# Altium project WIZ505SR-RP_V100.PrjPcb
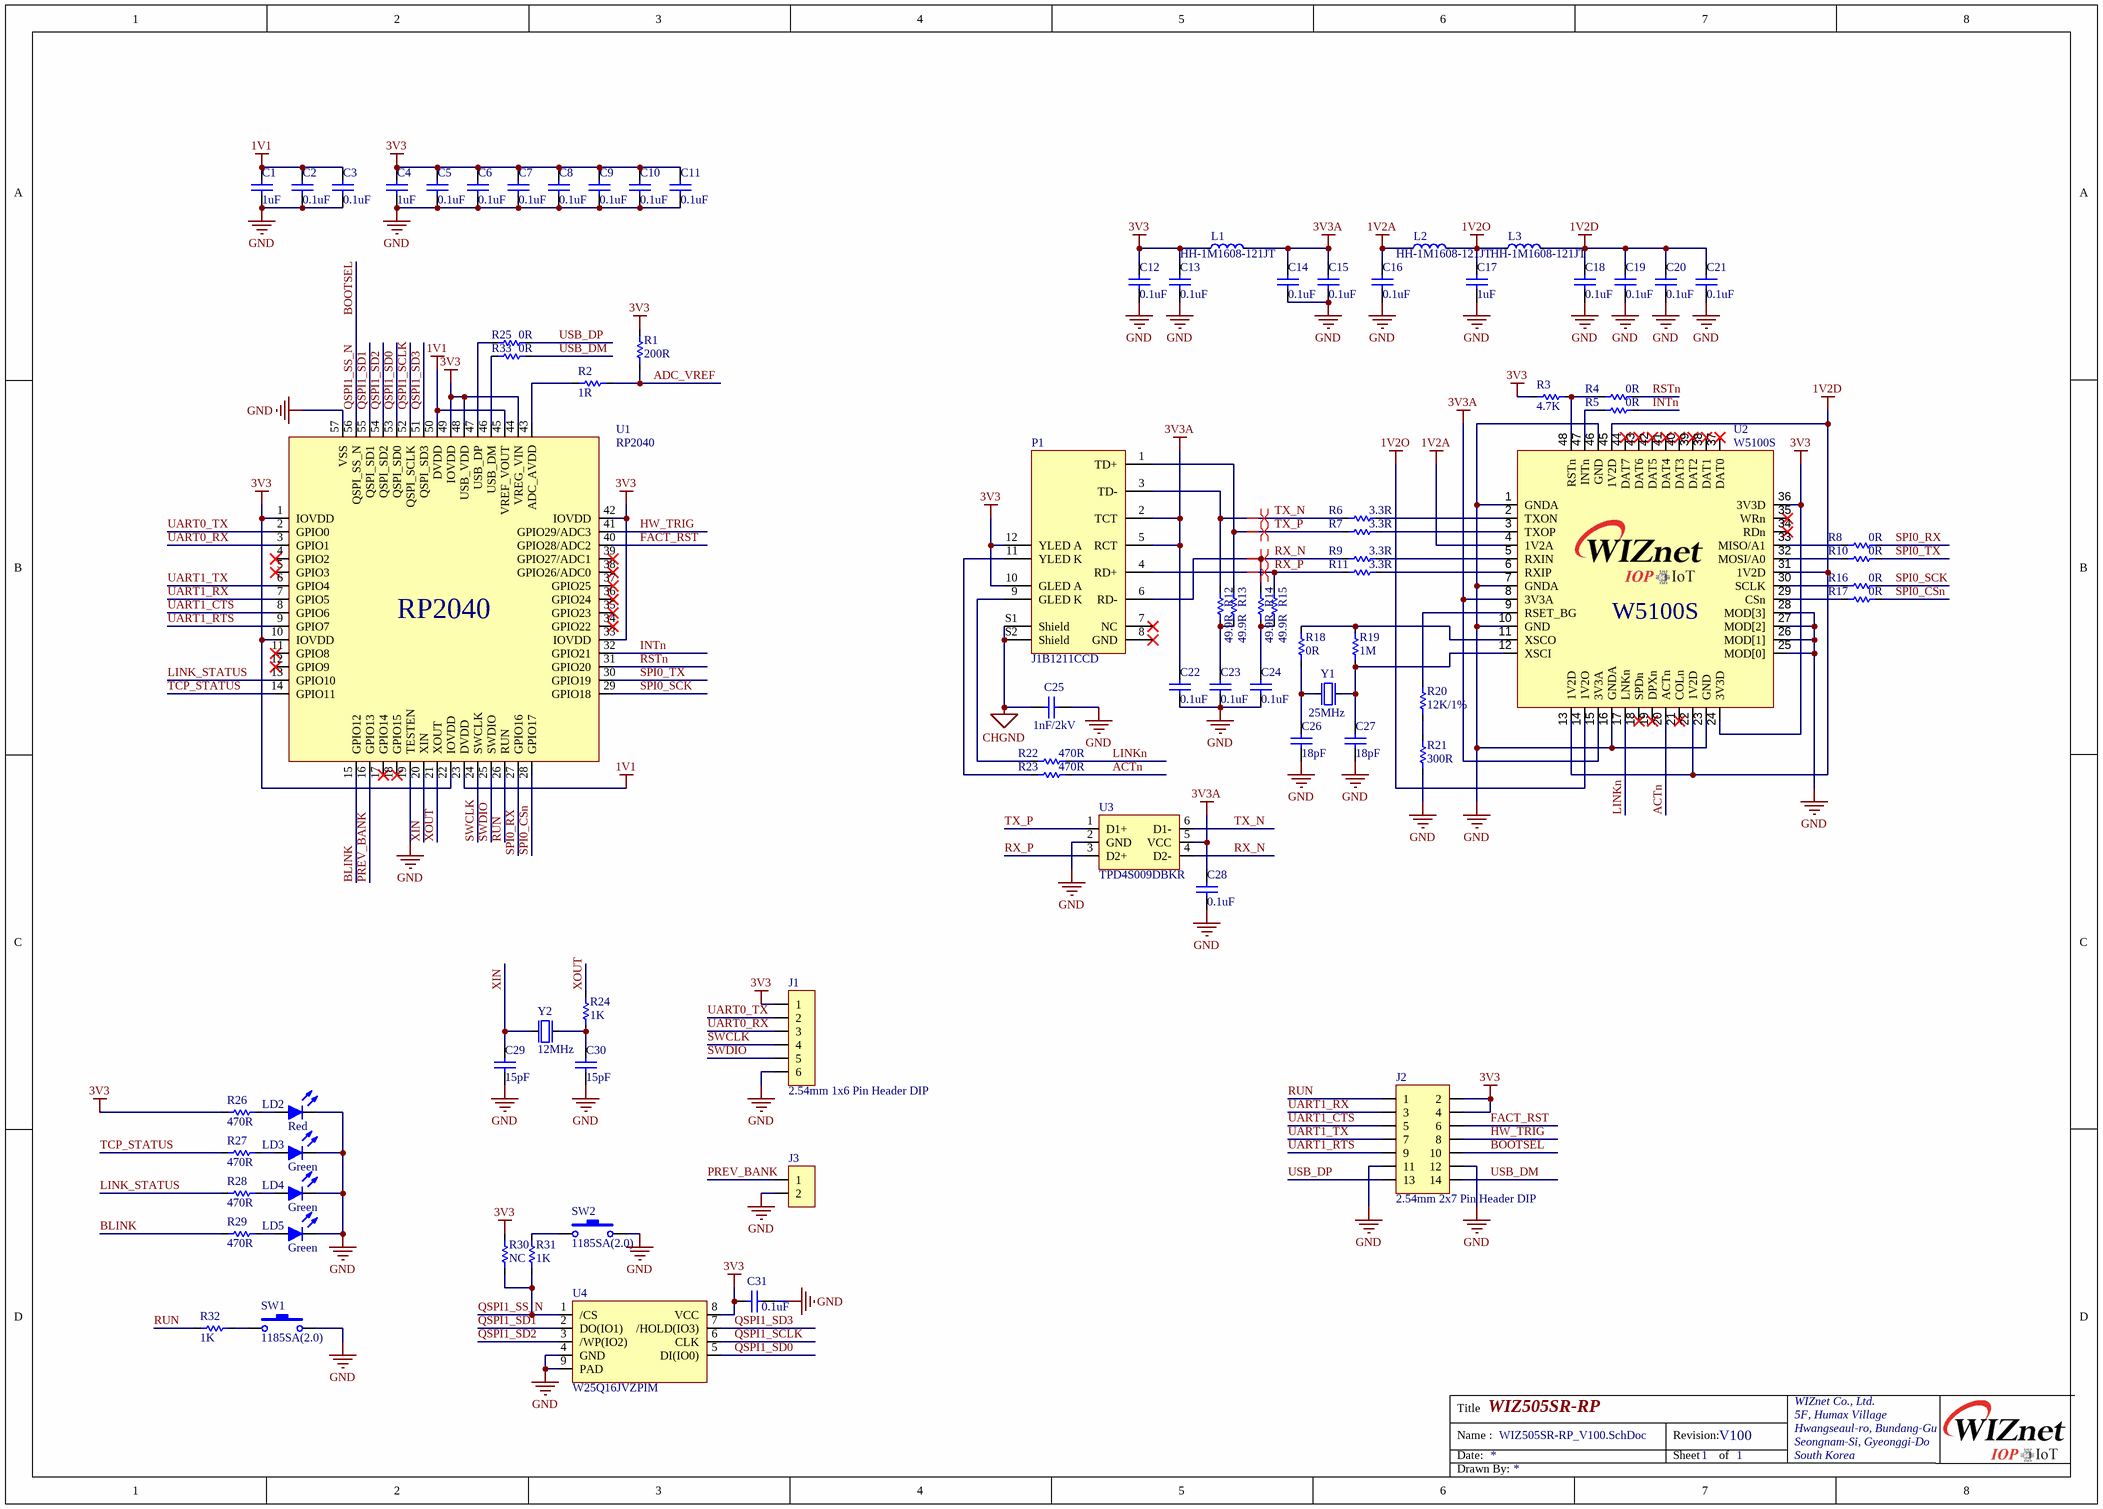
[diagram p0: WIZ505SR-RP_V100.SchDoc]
1 sheet, 83 parts. Net scope: global (net labels, ports and power ports of the same name join across sheets).
Board file: WIZ505SR-RP_V100.PcbDoc

## Sheet WIZ505SR-RP_V100.SchDoc: WIZ505SR-RP
size A3; Organization: WIZnet Co., Ltd.; Address1: 5F, Humax Village; Address2: Hwangseaul-ro, Bundang-Gu; Address3: Seongnam-Si, Gyeonggi-Do; Address4: South Korea; Revision: V100; SheetNumber: 1; SheetTotal: 1

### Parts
C1  1uF  [CAP-0402]
C2  0.1uF  [CAP-0402]
C3  0.1uF  [CAP-0402]
C4  1uF  [CAP-0402]
C5  0.1uF  [CAP-0402]
C6  0.1uF  [CAP-0402]
C7  0.1uF  [CAP-0402]
C8  0.1uF  [CAP-0402]
C9  0.1uF  [CAP-0402]
C10  0.1uF  [CAP-0402]
C11  0.1uF  [CAP-0402]
C12  0.1uF  [CAP-0402]
C13  0.1uF  [CAP-0402]
C14  0.1uF  [CAP-0402]
C15  0.1uF  [CAP-0402]
C16  0.1uF  [CAP-0402]
C17  1uF  [CAP-0402]
C18  0.1uF  [CAP-0402]
C19  0.1uF  [CAP-0402]
C20  0.1uF  [CAP-0402]
C21  0.1uF  [CAP-0402]
C22  0.1uF  [CAP-0402]
C23  0.1uF  [CAP-0402]
C24  0.1uF  [CAP-0402]
C25  1nF/2kV  [CAP-1808]
C26  18pF  [CAP-0402]
C27  18pF  [CAP-0402]
C28  0.1uF  [CAP-0402]
C29  15pF  [CAP-0402]
C30  15pF  [CAP-0402]
C31  0.1uF  [CAP-0402]
J1  2.54mm 1x6 Pin Header DIP  [IDC-1X6]
J2  2.54mm 2x7 Pin Header DIP  [IDC-2X7]
J3  2.54mm 1x2 Pin Header DIP  [IDC-1X2]  (value not drawn)
L1  HH-1M1608-121JT  [IND-0603]
L2  HH-1M1608-121JT  [IND-0603]
L3  HH-1M1608-121JT  [IND-0603]
LD2  Red  [LED-0603-green]
LD3  Green  [LED-0603-green]
LD4  Green  [LED-0603-green]
LD5  Green  [LED-0603-green]
P1  J1B1211CCD  [RJ45-J1B1211CCD]
R1  200R  [RES-0402]
R2  1R  [RES-0402]
R3  4.7K  [RES-0402]
R4  0R  [RES-0402]
R5  0R  [RES-0402]
R6  3.3R  [RES-0402]
R7  3.3R  [RES-0402]
R8  0R  [RES-0402]
R9  3.3R  [RES-0402]
R10  0R  [RES-0402]
R11  3.3R  [RES-0402]
R12  49.9R  [RES-0402]
R13  49.9R  [RES-0402]
R14  49.9R  [RES-0402]
R15  49.9R  [RES-0402]
R16  0R  [RES-0402]
R17  0R  [RES-0402]
R18  0R  [RES-0402]
R19  1M  [RES-0402]
R20  12K/1%  [RES-0402]
R21  300R  [RES-0402]
R22  470R  [RES-0402]
R23  470R  [RES-0402]
R24  1K  [RES-0402]
R25  0R  [RES-0402]
R26  470R  [RES-0402]
R27  470R  [RES-0402]
R28  470R  [RES-0402]
R29  470R  [RES-0402]
R30  NC  [RES-0402]
R31  1K  [RES-0402]
R32  1K  [RES-0402]
R33  0R  [RES-0402]
SW1  1185SA(2.0)  [ST-1185S]
SW2  1185SA(2.0)  [ST-1185S]
U1  RP2040  [RP2040_QFN56(0.4/7X7)]
U2  W5100S  [W5100S_LQFP48(0.5/9.0)]
U3  TPD4S009DBKR  [TPD4S009DBKR-SOT-23-6L]
U4  W25Q16JVZPIM  [WSON8(6X5_1.27)]
Y1  25MHz  [OSC-82J0626]
Y2  12MHz  [OSC-TZ1067B]

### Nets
1V1: C1.2 C2.2 C3.2 U1.23(DVDD) U1.45(VREF_VOUT) U1.50(DVDD)
1V2A: C16.2 L2.1 U2.4(1V2A)
1V2D: C18.2 C19.2 C20.2 C21.2 L3.2 U2.13(1V2D) U2.22(1V2D) U2.31(1V2D) U2.45(1V2D)
1V2O: C17.2 L2.2 L3.1 U2.14(1V2O)
3V3: C4.2 C5.2 C6.2 C7.2 C8.2 C9.2 C10.2 C11.2 C12.2 C13.2 C31.2 J1.1 J2.2 J2.4 L1.1 P1.10(GLED_A) P1.12(YLED_A) R1.1 R3.1 R26.2 R30.2 U1.1(IOVDD) U1.10(IOVDD) U1.22(IOVDD) U1.33(IOVDD) U1.42(IOVDD) U1.44(VREG_VIN) U1.48(USB_VDD) U1.49(IOVDD) U2.24(3V3D) U2.36(3V3D) U4.8(VCC)
3V3A: C14.2 C15.2 C22.2 C28.2 L1.2 P1.2(TCT) P1.5(RCT) U2.8(3V3A) U2.15(3V3A) U3.5(VCC)
CHGND: C25.2 P1.S1(Shield) P1.S2(Shield)
GND: C1.1 C2.1 C3.1 C4.1 C5.1 C6.1 C7.1 C8.1 C9.1 C10.1 C11.1 C12.1 C13.1 C14.1 C15.1 C16.1 C17.1 C18.1 C19.1 C20.1 C21.1 C22.1 C23.1 C24.1 C25.1 C26.1 C27.1 C28.1 C29.2 C30.2 C31.1 J1.6 J2.11 J2.12 J3.2 LD2.2(K) LD3.2(K) LD4.2(K) LD5.2(K) R21.2 SW1.2 SW2.2 U1.19(TESTEN) U1.57(VSS) U2.1(GNDA) U2.7(GNDA) U2.10(GND) U2.16(GNDA) U2.23(GND) U2.25(MOD[0]) U2.26(MOD[1]) U2.27(MOD[2]) U2.28(MOD[3]) U2.46(GND) U3.2(GND) U4.4(GND) U4.9(PAD) Y1.2(GND) Y1.4(GND) Y2.2 Y2.4
ACTn: R23.2 U2.20(ACTn)
ADC_VREF: R1.2 R2.2
BLINK: R29.2 U1.15(GPIO12)
BOOTSEL: J2.10 R30.1 R31.1 U1.56(QSPI_SS_N) U4.1(/CS)  [also labelled QSPI1_SS_N]
FACT_RST: J2.6 U1.40(GPIO28/ADC2)
HW_TRIG: J2.8 U1.41(GPIO29/ADC3)
INTn: R5.2 U1.32(GPIO21)
LINK_STATUS: R28.2 U1.13(GPIO10)
LINKn: R22.2 U2.17(LNKn)
PREV_BANK: J3.1 U1.16(GPIO13)
QSPI1_SCLK: U1.52(QSPI_SCLK) U4.6(CLK)
QSPI1_SD0: U1.53(QSPI_SD0) U4.5(DI(IO0))
QSPI1_SD1: U1.55(QSPI_SD1) U4.2(DO(IO1))
QSPI1_SD2: U1.54(QSPI_SD2) U4.3(/WP(IO2))
QSPI1_SD3: U1.51(QSPI_SD3) U4.7(/HOLD(IO3))
RSTn: R4.2 U1.31(GPIO20)
RUN: J2.1 R32.2 U1.26(RUN)
RX_N: P1.6(RD-) R9.1 R14.2 U3.4(D2-)
RX_P: P1.4(RD+) R11.1 R15.2 U3.3(D2+)
SPI0_CSn: R17.2 U1.28(GPIO17)
SPI0_RX: R8.2 U1.27(GPIO16)
SPI0_SCK: R16.2 U1.29(GPIO18)
SPI0_TX: R10.2 U1.30(GPIO19)
SWCLK: J1.4 U1.24(SWCLK)
SWDIO: J1.5 U1.25(SWDIO)
TCP_STATUS: R27.2 U1.14(GPIO11)
TX_N: P1.3(TD-) R6.1 R12.2 U3.6(D1-)
TX_P: P1.1(TD+) R7.1 R13.2 U3.1(D1+)
UART0_RX: J1.3 U1.3(GPIO1)
UART0_TX: J1.2 U1.2(GPIO0)
UART1_CTS: J2.5 U1.8(GPIO6)
UART1_RTS: J2.9 U1.9(GPIO7)
UART1_RX: J2.3 U1.7(GPIO5)
UART1_TX: J2.7 U1.6(GPIO4)
USB_DM: J2.14 R33.1
USB_DP: J2.13 R25.1
XIN: C29.1 U1.20(XIN) Y2.1(inp)
XOUT: R24.2 U1.21(XOUT)
NetC23_2: C23.2 R12.1 R13.1
NetC24_2: C24.2 R14.1 R15.1
NetC26_2: C26.2 R18.1 Y1.1(inp)
NetC27_2: C27.2 R19.1 U2.12(XSCI) Y1.3(out)
NetC30_1: C30.1 R24.1 Y2.3(out)
NetLD2_1: LD2.1(A) R26.1
NetLD3_1: LD3.1(A) R27.1
NetLD4_1: LD4.1(A) R28.1
NetLD5_1: LD5.1(A) R29.1
NetP1_9: P1.9(GLED_K) R22.1
NetP1_11: P1.11(YLED_K) R23.1
NetR2_1: R2.1 U1.43(ADC_AVDD)
NetR3_2: R3.2 R4.1 U2.48(RSTn)
NetR5_1: R5.1 U2.47(INTn)
NetR6_2: R6.2 U2.2(TXON)
NetR7_2: R7.2 U2.3(TXOP)
NetR8_1: R8.1 U2.33(MISO/A1)
NetR9_2: R9.2 U2.5(RXIN)
NetR10_1: R10.1 U2.32(MOSI/A0)
NetR11_2: R11.2 U2.6(RXIP)
NetR16_1: R16.1 U2.30(SCLK)
NetR17_1: R17.1 U2.29(CSn)
NetR18_2: R18.2 R19.2 U2.11(XSCO)
NetR20_1: R20.1 U2.9(RSET_BG)
NetR20_2: R20.2 R21.1
NetR25_2: R25.2 U1.47(USB_DP)
NetR31_2: R31.2 SW2.1
NetR32_1: R32.1 SW1.1
NetR33_2: R33.2 U1.46(USB_DM)

Not connected (* = marked no-connect by the designer): P1 7(NC)* 8(GND)*; U1 4(GPIO2)* 5(GPIO3)* 11(GPIO8)* 12(GPIO9)* 17(GPIO14)* 18(GPIO15)* 34(GPIO22)* 35(GPIO23)* 36(GPIO24)* 37(GPIO25)* 38(GPIO26/ADC0)* 39(GPIO27/ADC1)*; U2 18(SPDn)* 19(DPXn)* 21(COLn)* 34(RDn)* 35(WRn)* 37(DAT0)* 38(DAT1)* 39(DAT2)* 40(DAT3)* 41(DAT4)* 42(DAT5)* 43(DAT6)* 44(DAT7)*

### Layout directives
differential pair: RX_N, RX_P, TX_N, TX_P

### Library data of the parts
C1-C24 C26-C31 = CAP-0402: Ceramic CAP 0402(1005)
C25 = CAP-1808: Ceramic CAP 1808(4520)
L1-L3 = IND-0603: Inductor 0603(1608)
LD2-LD5 = LED-0603
R1-R33 = RES-0402
SW1 SW2 = ITS-1107(SMD): TACT Switch (SMD)
U1 = RP2040: Raspverry Pi, Dual ARM Cortex-M0+ @ 133MHz
U2 = W5100S: WIZnet Hardwired TCP/IP Chip
U3 = TPD4S009DBKR: 4-Channel ESD Solution for High-Speed Differential Interface
U4 = W25Q16JVZPIM: 3V 16M-BIT / SERIAL FLASH MEMORY WITH / DUAL/QUAD SPI, QPI & DTR
Y1 = OSC-82J0626-25MHz: X-tal 25MHz,3.2x2.5 SMD, CL=18pF
Y2 = OSC-TZ1067B-12MHz: X-tal 12MHz,3.2x2.5 SMD, CL=20pF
